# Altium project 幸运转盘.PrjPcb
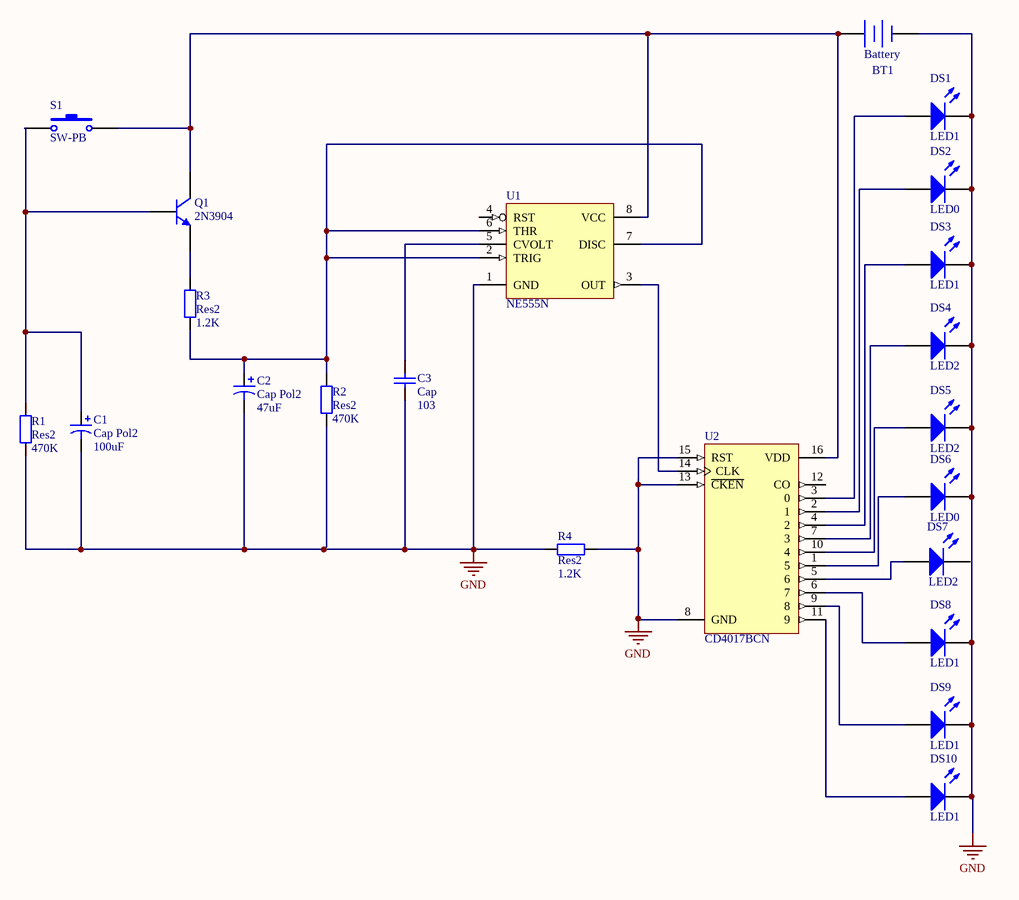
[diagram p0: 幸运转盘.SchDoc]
1 sheet, 22 parts. Net scope: global (net labels, ports and power ports of the same name join across sheets).
Board file: 幸运转盘.PcbDoc

## Sheet 幸运转盘.SchDoc
size A4

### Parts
BT1  Battery  [BAT-2]
C1  Cap Pol2  value 100uF  [电解电容100uF]
C2  Cap Pol2  value 47uF  [电解电容47uF]
C3  Cap  value 103  [CAPR2.54-5.1X3.2]
DS1  LED1  [发光二极管]
DS2  LED0  [发光二极管]
DS3  LED1  [发光二极管]
DS4  LED2  [发光二极管]
DS5  LED2  [发光二极管]
DS6  LED0  [发光二极管]
DS7  LED2  [发光二极管]
DS8  LED1  [发光二极管]
DS9  LED1  [发光二极管]
DS10  LED1  [发光二极管]
Q1  2N3904  [TO-92]
R1  Res2  value 470K  [AXIAL-0.4]
R2  Res2  value 470K  [AXIAL-0.4]
R3  Res2  value 1.2K  [AXIAL-0.4]
R4  Res2  value 1.2K  [AXIAL-0.4]
S1  SW-PB  [轻触开关]
U1  NE555N  [NE555]
U2  CD4017BCN  [CD4017]

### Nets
GND: BT1.2(-) C1.2 C2.2 C3.1 DS1.2(K) DS2.2(K) DS3.2(K) DS4.2(K) DS5.2(K) DS6.2(K) DS8.2(K) DS9.2(K) DS10.2(K) R1.1 R2.1 R4.1 R4.2 U1.1(GND) U2.8(GND) U2.13(~{CKEN}) U2.15(RST)
NetBT1_1: BT1.1(+) Q1.3(C) S1.2 U1.8(VCC) U2.16(VDD)
NetC1_1: C1.1 Q1.2(B) R1.2 S1.1
NetC2_1: C2.1 R2.2 R3.1 U1.2(TRIG) U1.6(THR) U1.7(DISC)
NetC3_2: C3.2 U1.5(CVOLT)
NetDS1_1: DS1.1(A) U2.3(0)
NetDS2_1: DS2.1(A) U2.2(1)
NetDS3_1: DS3.1(A) U2.4(2)
NetDS4_1: DS4.1(A) U2.7(3)
NetDS5_1: DS5.1(A) U2.10(4)
NetDS6_1: DS6.1(A) U2.1(5)
NetDS7_1: DS7.1(A) U2.5(6)
NetDS8_1: DS8.1(A) U2.6(7)
NetDS9_1: DS9.1(A) U2.9(8)
NetDS10_1: DS10.1(A) U2.11(9)
NetQ1_1: Q1.1(E) R3.2
NetU1_3: U1.3(OUT) U2.14(CLK)

Not connected (* = marked no-connect by the designer): DS7 2(K); U1 4(RST); U2 12(CO)

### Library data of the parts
BT1 = Battery: Multicell Battery
C1 C2 = Cap Pol2: Polarized Capacitor (Axial)
C3 = Cap: Capacitor
DS1 DS3 DS8-DS10 = LED1: Typical RED GaAs LED
DS2 DS6 = LED0: Typical INFRARED GaAs LED
DS4 DS5 DS7 = LED2: Typical RED, GREEN, YELLOW, AMBER GaAs LED
Q1 = 2N3904: NPN General Purpose Amplifier; Revision 1: 11-Jul-2000: SIM Model Added.; Revision 2: 17-Jul-2002: Re-released for DXP Platform.; Revision 3: 15-Jan-2003: PCB Footprint 'BCY-W3/D4.7' replaced; Code - JEDEC: TO-92A
R1-R4 = Res2: Resistor
S1 = SW-PB: Switch
U1 = NE555N: General-Purpose Single Bipolar Timer; Code - JEDEC: MO-001-AN
U2 = CD4017BCN: Decade Counter/Divider with 10 Decoded Outputs; Package Information: Latest Revision: 2000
